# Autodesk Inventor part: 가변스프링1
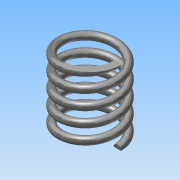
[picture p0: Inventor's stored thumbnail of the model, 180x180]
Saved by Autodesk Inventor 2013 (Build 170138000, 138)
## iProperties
Created: 2015-02
Part Number: 가변스프링1
Material: 강철, 탄소
Document SubType Name: Modeling
Designer: WINDOWS7
Density: 7.87 g/cm^3
Mass: 18.9085 g
Surface Area: 32.5528 cm^2
Volume: 2.40261 cm^3
Author: WINDOWS7
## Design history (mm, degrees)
sketch "스케치1"
  geometry: L1 (0, 0)-(11, 0); L2 (11, 0)-(11, 40.095); L3 (11, 40.095)-(0, 40.095); L4 (0, 40.095)-(0, 0); C1 r 1.5 at (11, 0)
  constraints: 8 end point, 2 parallel, 1 centre point, 1 coincident, 1 horizontal, 1 perpendicular
  dimensions: "d0" = 3 diameter of C1; "d2" = 22 diameter of L2 L4; "d3" = 40.0955 distance between parallel lines of L1 L3 (derived)
feature "코일1" sketch "스케치1" pitch "d4" = 10; turns "d6" = 5; dims "d5" = 40.0955 (= d3), "d7" = 0, angle "d8" = 90 deg, angle "d9" = 90 deg, "d10" = 0, "d11" = 0
feature "분할1"
node "작업 평면1"
feature "분할2"
node "솔리드1"
other parameters: "d12" = 90 deg
